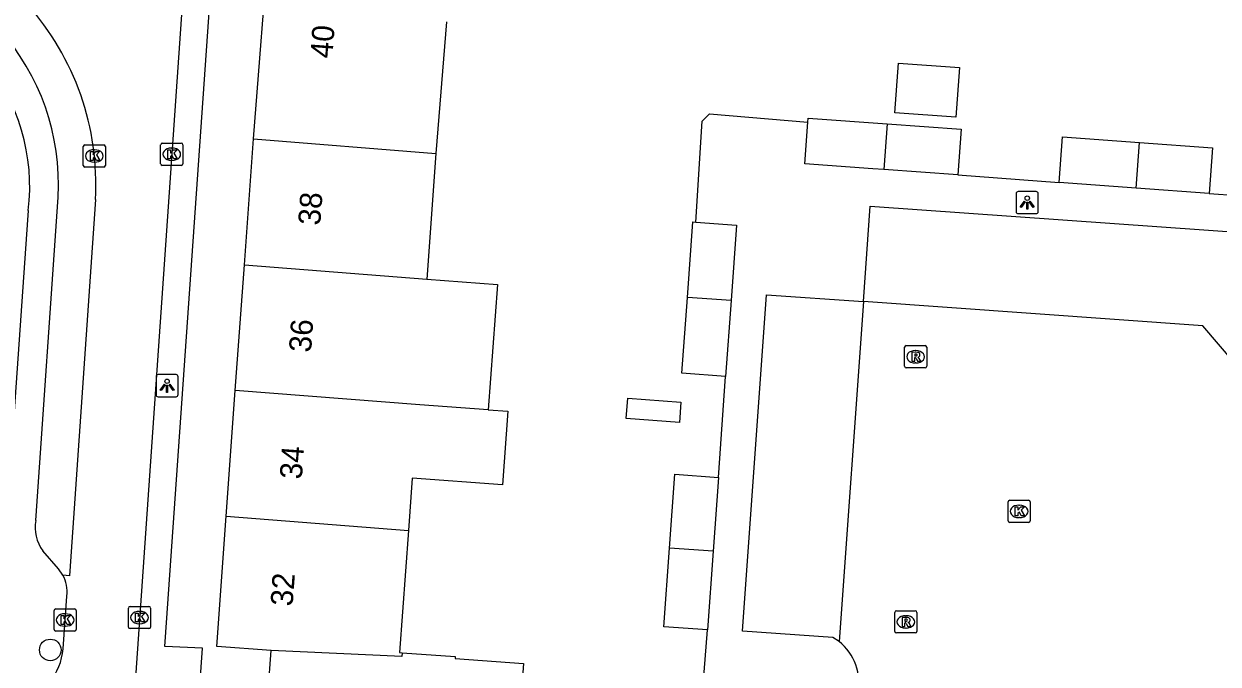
# Model space of a CAD drawing. Extents: x 160304 to 160954, y 383686 to 384161.
# Drawn here: x 160524.6 to 160578.4, y 384097.6 to 384126.5 of the extents above; entities that cross this region are included whole.
import ezdxf

# ---------------------------------------------------------------- set-up
doc = ezdxf.new("R2010")
doc.units = 0
for name, color, linetype in [('IMGEO_Boom', 7, 'Continuous'), ('IMGEO_Kolk', 7, 'Continuous'), ('IMGEO_Lichtpunt', 7, 'Continuous'), ('IMGEO_Pand', 7, 'Continuous'), ('IMGEO_Pand_nummerreeks', 7, 'Continuous'), ('IMGEO_Rijbaan_lokaal_open', 7, 'Continuous'), ('IMGEO_Rioolput', 7, 'Continuous'), ('IMGEO_Voetpad_open', 7, 'Continuous')]:
    doc.layers.add(name, color=color, linetype=linetype)

msp = doc.modelspace()

# ---------------------------------------------------------------- linework, layer by layer
at = {"layer": 'IMGEO_Boom'}
msp.add_circle((160525.753, 384098.271), 0.489, dxfattribs=at)
at = {"layer": 'IMGEO_Kolk'}
for p, q in [((160527.239, 384120.118), (160527.239, 384120.97)), ((160527.314, 384121.044), (160528.166, 384121.044)), ((160527.727, 384120.824), (160527.752, 384120.824)), ((160528.24, 384120.97), (160528.24, 384120.118)), ((160530.729, 384120.196), (160530.729, 384121.048)), ((160530.804, 384121.122), (160531.656, 384121.122)), ((160531.217, 384120.902), (160531.242, 384120.902)), ((160531.73, 384121.048), (160531.73, 384120.196)), ((160527.75, 384120.264), (160527.725, 384120.264)), ((160531.24, 384120.342), (160531.215, 384120.342)), ((160528.166, 384120.044), (160527.314, 384120.044)), ((160531.656, 384120.122), (160530.804, 384120.122)), ((160568.938, 384104.095), (160568.938, 384104.947)), ((160569.013, 384105.021), (160569.865, 384105.021)), ((160569.426, 384104.801), (160569.451, 384104.801)), ((160569.939, 384104.947), (160569.939, 384104.095)), ((160569.449, 384104.241), (160569.424, 384104.241)), ((160569.865, 384104.021), (160569.013, 384104.021)), ((160525.921, 384099.197), (160525.921, 384100.049)), ((160525.996, 384100.123), (160526.848, 384100.123)), ((160526.409, 384099.903), (160526.434, 384099.903)), ((160526.922, 384100.049), (160526.922, 384099.197)), ((160529.276, 384099.307), (160529.276, 384100.159)), ((160529.351, 384100.233), (160530.203, 384100.233)), ((160529.764, 384100.013), (160529.789, 384100.013)), ((160530.277, 384100.159), (160530.277, 384099.307)), ((160526.432, 384099.343), (160526.407, 384099.343)), ((160529.787, 384099.453), (160529.762, 384099.453)), ((160526.848, 384099.123), (160525.996, 384099.123)), ((160530.203, 384099.233), (160529.351, 384099.233))]:
    msp.add_line(p, q, dxfattribs=at)
for points in [[(160527.239, 384120.118), (160527.239, 384120.97)], [(160527.314, 384121.044), (160528.166, 384121.044)], [(160528.24, 384120.97), (160528.24, 384120.118)], [(160530.729, 384120.196), (160530.729, 384121.048)], [(160530.804, 384121.122), (160531.656, 384121.122)], [(160531.05, 384120.822), (160531.173, 384120.822), (160531.173, 384120.671), (160531.303, 384120.822), (160531.467, 384120.822), (160531.321, 384120.671), (160531.474, 384120.422), (160531.322, 384120.422), (160531.237, 384120.586), (160531.173, 384120.519), (160531.173, 384120.422), (160531.05, 384120.422), (160531.05, 384120.822)], [(160531.73, 384121.048), (160531.73, 384120.196)], [(160527.56, 384120.744), (160527.683, 384120.744), (160527.683, 384120.593), (160527.813, 384120.744), (160527.977, 384120.744), (160527.831, 384120.593), (160527.984, 384120.344), (160527.832, 384120.344), (160527.747, 384120.508), (160527.683, 384120.441), (160527.683, 384120.344), (160527.56, 384120.344), (160527.56, 384120.744)], [(160528.166, 384120.044), (160527.314, 384120.044)], [(160531.656, 384120.122), (160530.804, 384120.122)], [(160568.938, 384104.095), (160568.938, 384104.947)], [(160569.013, 384105.021), (160569.865, 384105.021)], [(160569.259, 384104.721), (160569.382, 384104.721), (160569.382, 384104.57), (160569.512, 384104.721), (160569.676, 384104.721), (160569.53, 384104.57), (160569.683, 384104.321), (160569.531, 384104.321), (160569.446, 384104.485), (160569.382, 384104.418), (160569.382, 384104.321), (160569.259, 384104.321), (160569.259, 384104.721)], [(160569.939, 384104.947), (160569.939, 384104.095)], [(160569.865, 384104.021), (160569.013, 384104.021)], [(160525.921, 384099.197), (160525.921, 384100.049)], [(160525.996, 384100.123), (160526.848, 384100.123)], [(160526.242, 384099.823), (160526.365, 384099.823), (160526.365, 384099.672), (160526.495, 384099.823), (160526.659, 384099.823), (160526.513, 384099.672), (160526.666, 384099.423), (160526.514, 384099.423), (160526.429, 384099.587), (160526.365, 384099.52), (160526.365, 384099.423), (160526.242, 384099.423), (160526.242, 384099.823)], [(160526.922, 384100.049), (160526.922, 384099.197)], [(160529.276, 384099.307), (160529.276, 384100.159)], [(160529.351, 384100.233), (160530.203, 384100.233)], [(160529.597, 384099.933), (160529.72, 384099.933), (160529.72, 384099.782), (160529.85, 384099.933), (160530.014, 384099.933), (160529.868, 384099.782), (160530.021, 384099.533), (160529.869, 384099.533), (160529.784, 384099.697), (160529.72, 384099.63), (160529.72, 384099.533), (160529.597, 384099.533), (160529.597, 384099.933)], [(160530.277, 384100.159), (160530.277, 384099.307)], [(160526.848, 384099.123), (160525.996, 384099.123)], [(160530.203, 384099.233), (160529.351, 384099.233)]]:
    msp.add_lwpolyline(points, dxfattribs=at)
for centre, start, end in [((160527.316, 384120.968), 91.552, 178.448), ((160527.316, 384120.968), 91.552, 178.448), ((160528.164, 384120.968), 1.552, 88.448), ((160528.164, 384120.968), 1.552, 88.448), ((160530.806, 384121.046), 91.552, 178.448), ((160530.806, 384121.046), 91.552, 178.448), ((160531.654, 384121.046), 1.552, 88.448), ((160531.654, 384121.046), 1.552, 88.448), ((160527.316, 384120.12), 181.552, 268.448), ((160527.316, 384120.12), 181.552, 268.448), ((160528.164, 384120.12), 271.552, 358.448), ((160528.164, 384120.12), 271.552, 358.448), ((160530.806, 384120.198), 181.552, 268.448), ((160530.806, 384120.198), 181.552, 268.448), ((160531.654, 384120.198), 271.552, 358.448), ((160531.654, 384120.198), 271.552, 358.448), ((160569.015, 384104.945), 91.552, 178.448), ((160569.015, 384104.945), 91.552, 178.448), ((160569.863, 384104.945), 1.552, 88.448), ((160569.863, 384104.945), 1.552, 88.448), ((160569.015, 384104.097), 181.552, 268.448), ((160569.015, 384104.097), 181.552, 268.448), ((160569.863, 384104.097), 271.552, 358.448), ((160569.863, 384104.097), 271.552, 358.448), ((160525.998, 384100.047), 91.552, 178.448), ((160525.998, 384100.047), 91.552, 178.448), ((160526.846, 384100.047), 1.552, 88.448), ((160526.846, 384100.047), 1.552, 88.448), ((160529.353, 384100.157), 91.552, 178.448), ((160529.353, 384100.157), 91.552, 178.448), ((160530.201, 384100.157), 1.552, 88.448), ((160530.201, 384100.157), 1.552, 88.448), ((160529.353, 384099.309), 181.552, 268.448), ((160529.353, 384099.309), 181.552, 268.448), ((160530.201, 384099.309), 271.552, 358.448), ((160530.201, 384099.309), 271.552, 358.448), ((160525.998, 384099.199), 181.552, 268.448), ((160525.998, 384099.199), 181.552, 268.448), ((160526.846, 384099.199), 271.552, 358.448), ((160526.846, 384099.199), 271.552, 358.448)]:
    msp.add_arc(centre, 0.0765, start, end, dxfattribs=at)
for centre, major_axis, ratio, start_param, end_param in [((160527.726, 384120.544), (-0.387, 0.002), 0.722429, 4.712389, 7.853982), ((160527.751, 384120.544), (-0.39, 0.002), 0.717154, 1.570796, 4.712389), ((160531.216, 384120.622), (-0.387, 0.002), 0.722429, 4.712389, 7.853982), ((160531.241, 384120.622), (-0.39, 0.002), 0.717154, 1.570796, 4.712389), ((160569.425, 384104.521), (-0.387, 0.002), 0.722429, 4.712389, 7.853982), ((160569.45, 384104.521), (-0.39, 0.002), 0.717154, 1.570796, 4.712389), ((160526.408, 384099.623), (-0.387, 0.002), 0.722429, 4.712389, 7.853982), ((160526.433, 384099.623), (-0.39, 0.002), 0.717154, 1.570796, 4.712389), ((160529.763, 384099.733), (-0.387, 0.002), 0.722429, 4.712389, 7.853982), ((160529.788, 384099.733), (-0.39, 0.002), 0.717154, 1.570796, 4.712389)]:
    msp.add_ellipse(centre, major_axis=major_axis, ratio=ratio, start_param=start_param, end_param=end_param, dxfattribs=at)
at = {"layer": 'IMGEO_Lichtpunt'}
for p, q in [((160569.302, 384118.845), (160569.302, 384118.038)), ((160569.302, 384118.845), (160569.302, 384118.038)), ((160570.204, 384118.94), (160569.396, 384118.94)), ((160570.204, 384118.94), (160569.396, 384118.94)), ((160570.298, 384118.038), (160570.298, 384118.845)), ((160570.298, 384118.038), (160570.298, 384118.845)), ((160569.396, 384117.944), (160570.204, 384117.944)), ((160569.396, 384117.944), (160570.204, 384117.944)), ((160530.521, 384110.59), (160530.521, 384109.783)), ((160530.521, 384110.59), (160530.521, 384109.783)), ((160531.423, 384110.685), (160530.615, 384110.685)), ((160531.423, 384110.685), (160530.615, 384110.685)), ((160531.517, 384109.783), (160531.517, 384110.59)), ((160531.517, 384109.783), (160531.517, 384110.59)), ((160530.615, 384109.689), (160531.423, 384109.689)), ((160530.615, 384109.689), (160531.423, 384109.689))]:
    msp.add_line(p, q, dxfattribs=at)
for points in [[(160569.676, 384118.509), (160569.715, 384118.481), (160569.527, 384118.219), (160569.489, 384118.246), (160569.676, 384118.509)], [(160569.778, 384118.461), (160569.825, 384118.461), (160569.825, 384118.139), (160569.778, 384118.139), (160569.778, 384118.461)], [(160569.888, 384118.481), (160569.926, 384118.508), (160570.113, 384118.246), (160570.074, 384118.218), (160569.888, 384118.481)], [(160530.895, 384110.254), (160530.934, 384110.226), (160530.746, 384109.964), (160530.708, 384109.991), (160530.895, 384110.254)], [(160530.997, 384110.206), (160531.044, 384110.206), (160531.044, 384109.884), (160530.997, 384109.884), (160530.997, 384110.206)], [(160531.107, 384110.226), (160531.145, 384110.253), (160531.332, 384109.991), (160531.293, 384109.963), (160531.107, 384110.226)]]:
    msp.add_lwpolyline(points, dxfattribs=at)
for centre in [(160569.801, 384118.643), (160531.02, 384110.388)]:
    msp.add_circle(centre, 0.0994, dxfattribs=at)
for centre, start, end in [((160569.396, 384118.845), 90, 180), ((160569.396, 384118.845), 90, 180), ((160570.204, 384118.845), 0, 90), ((160570.204, 384118.845), 0, 90), ((160569.396, 384118.038), 180, 270), ((160569.396, 384118.038), 180, 270), ((160570.204, 384118.038), 270, 0), ((160570.204, 384118.038), 270, 360), ((160530.615, 384110.59), 90, 180), ((160530.615, 384110.59), 90, 180), ((160531.423, 384110.59), 0, 90), ((160531.423, 384110.59), 0, 90), ((160530.615, 384109.783), 180, 270), ((160530.615, 384109.783), 180, 270), ((160531.423, 384109.783), 270, 0), ((160531.423, 384109.783), 270, 360)]:
    msp.add_arc(centre, 0.0946, start, end, dxfattribs=at)
at = {"layer": 'IMGEO_Pand'}
for points in [[(160534.918, 384121.312), (160535.658, 384130.704)], [(160543.616, 384126.592), (160543.136, 384120.655)], [(160563.834, 384122.489), (160563.993, 384124.731), (160566.742, 384124.537), (160566.584, 384122.294), (160563.834, 384122.489)], [(160563.338, 384119.93), (160562.837, 384119.966), (160559.78, 384120.188), (160559.916, 384122.067)], [(160559.916, 384122.067), (160559.93, 384122.255), (160563.484, 384121.997)], [(160563.484, 384121.997), (160563.338, 384119.93)], [(160563.484, 384121.997), (160566.826, 384121.755), (160566.676, 384119.688)], [(160571.242, 384119.346), (160571.391, 384121.402), (160574.859, 384121.151)], [(160534.507, 384115.643), (160534.918, 384121.312)], [(160534.918, 384121.312), (160543.136, 384120.655)], [(160574.718, 384119.094), (160574.859, 384121.151)], [(160574.859, 384121.151), (160578.16, 384120.912), (160578.011, 384118.856)], [(160543.136, 384120.655), (160542.725, 384114.987)], [(160566.676, 384119.688), (160563.338, 384119.93)], [(160574.718, 384119.094), (160571.242, 384119.346)], [(160578.011, 384118.856), (160574.718, 384119.094)], [(160554.476, 384114.169), (160554.723, 384117.573), (160554.858, 384117.563)], [(160554.858, 384117.563), (160556.695, 384117.43), (160556.449, 384114.031)], [(160534.096, 384109.976), (160534.507, 384115.643)], [(160534.507, 384115.643), (160542.725, 384114.987)], [(160542.725, 384114.987), (160545.913, 384114.756), (160545.503, 384109.097)], [(160556.2, 384110.603), (160554.227, 384110.746), (160554.476, 384114.169)], [(160556.449, 384114.031), (160554.476, 384114.169)], [(160556.449, 384114.031), (160556.2, 384110.603)], [(160533.684, 384104.304), (160534.096, 384109.976)], [(160545.503, 384109.097), (160542.41, 384109.32), (160534.096, 384109.976)], [(160554.116, 384108.53), (160551.725, 384108.704), (160551.792, 384109.625), (160554.183, 384109.451), (160554.116, 384108.53)], [(160545.503, 384109.097), (160546.387, 384109.033), (160546.147, 384105.723), (160542.074, 384106.018), (160541.903, 384103.658)], [(160553.675, 384102.864), (160553.916, 384106.191), (160555.881, 384106.048)], [(160555.881, 384106.048), (160555.641, 384102.731)], [(160535.71, 384098.248), (160533.258, 384098.425), (160533.684, 384104.304)], [(160533.684, 384104.304), (160541.903, 384103.658)], [(160541.903, 384103.658), (160541.504, 384098.152), (160541.621, 384098.144)], [(160555.383, 384099.177), (160553.418, 384099.32), (160553.675, 384102.864)], [(160555.641, 384102.731), (160553.675, 384102.864)], [(160555.641, 384102.731), (160555.383, 384099.177)], [(160535.311, 384092.74), (160535.71, 384098.248)], [(160541.621, 384098.144), (160541.61, 384097.97), (160535.71, 384098.248)], [(160541.621, 384098.144), (160544.014, 384097.97), (160544.008, 384097.884), (160547.083, 384097.661), (160546.654, 384091.741), (160543.578, 384091.964)]]:
    msp.add_lwpolyline(points, dxfattribs=at)
at = {"layer": 'IMGEO_Rijbaan_lokaal_open'}
for points in [[(160537.481, 384138.035), (160534.196, 384135.168), (160533.788, 384134.809), (160533.414, 384134.416), (160533.076, 384133.99), (160532.778, 384133.536), (160532.521, 384133.058), (160532.308, 384132.558), (160532.141, 384132.041), (160532.021, 384131.511), (160531.948, 384130.973), (160531.927, 384130.626), (160529.545, 384096.378), (160529.643, 384095.449)], [(160527.788, 384118.582), (160526.612, 384101.616), (160526.321, 384101.646)], [(160562.416, 384113.979), (160561.315, 384098.651)], [(160584.868, 384104.518), (160577.716, 384112.888), (160562.416, 384113.979)], [(160526.335, 384098.318), (160526.497, 384100.704)]]:
    msp.add_lwpolyline(points, dxfattribs=at)
for centre, radius, start, end in [((160515.64, 384119.275), 12.168, 356.7331, 41.8412), ((160524.968, 384100.906), 1.543, 352.4883, 28.6775), ((160523.525, 384098.596), 2.824, 320.8869, 354.3452), ((160559.948, 384096.863), 2.251, 345.8903, 52.6046)]:
    msp.add_arc(centre, radius, start, end, dxfattribs=at)
at = {"layer": 'IMGEO_Rioolput'}
for p, q in [((160564.268, 384111.066), (160564.268, 384111.918)), ((160564.343, 384111.992), (160565.195, 384111.992)), ((160564.756, 384111.772), (160564.781, 384111.772)), ((160565.269, 384111.918), (160565.269, 384111.066)), ((160564.779, 384111.212), (160564.754, 384111.212)), ((160565.195, 384110.992), (160564.343, 384110.992)), ((160563.828, 384099.111), (160563.828, 384099.963)), ((160563.903, 384100.037), (160564.755, 384100.037)), ((160564.316, 384099.817), (160564.341, 384099.817)), ((160564.829, 384099.963), (160564.829, 384099.111)), ((160564.339, 384099.257), (160564.314, 384099.257)), ((160564.755, 384099.037), (160563.903, 384099.037))]:
    msp.add_line(p, q, dxfattribs=at)
for points in [[(160564.268, 384111.066), (160564.268, 384111.918)], [(160564.343, 384111.992), (160565.195, 384111.992)], [(160564.857, 384111.69), (160564.605, 384111.692), (160564.605, 384111.292)], [(160565.269, 384111.918), (160565.269, 384111.066)], [(160564.605, 384111.292), (160564.729, 384111.292), (160564.729, 384111.454), (160564.74, 384111.454)], [(160564.783, 384111.611), (160564.729, 384111.611), (160564.729, 384111.53)], [(160564.729, 384111.53), (160564.781, 384111.53)], [(160564.787, 384111.425), (160564.858, 384111.292), (160564.998, 384111.292), (160564.933, 384111.418)], [(160565.195, 384110.992), (160564.343, 384110.992)], [(160563.828, 384099.111), (160563.828, 384099.963)], [(160563.903, 384100.037), (160564.755, 384100.037)], [(160564.829, 384099.963), (160564.829, 384099.111)], [(160564.417, 384099.735), (160564.165, 384099.737), (160564.165, 384099.337)], [(160564.165, 384099.337), (160564.289, 384099.337), (160564.289, 384099.499), (160564.3, 384099.499)], [(160564.343, 384099.656), (160564.289, 384099.656), (160564.289, 384099.575)], [(160564.289, 384099.575), (160564.341, 384099.575)], [(160564.347, 384099.47), (160564.418, 384099.337), (160564.558, 384099.337), (160564.493, 384099.463)], [(160564.755, 384099.037), (160563.903, 384099.037)]]:
    msp.add_lwpolyline(points, dxfattribs=at)
for centre, radius, start, end in [((160564.345, 384111.916), 0.0765, 91.552, 178.448), ((160564.345, 384111.916), 0.0765, 91.552, 178.448), ((160564.856, 384111.58), 0.109, 350.3612, 89.416), ((160565.193, 384111.916), 0.0765, 1.552, 88.448), ((160565.193, 384111.916), 0.0765, 1.552, 88.448), ((160564.739, 384111.401), 0.0533, 26.0293, 88.6989), ((160564.765, 384111.719), 0.19, 274.7715, 282.9687), ((160564.789, 384111.515), 0.0964, 77.0061, 93.1865), ((160564.803, 384111.572), 0.0378, 276.6634, 79.6772), ((160564.854, 384111.58), 0.112, 277.5842, 350.9817), ((160564.838, 384111.365), 0.108, 29.5134, 73.7905), ((160564.345, 384111.068), 0.0765, 181.552, 268.448), ((160564.345, 384111.068), 0.0765, 181.552, 268.448), ((160565.193, 384111.068), 0.0765, 271.552, 358.448), ((160565.193, 384111.068), 0.0765, 271.552, 358.448), ((160563.905, 384099.961), 0.0765, 91.552, 178.448), ((160563.905, 384099.961), 0.0765, 91.552, 178.448), ((160564.753, 384099.961), 0.0765, 1.552, 88.448), ((160564.753, 384099.961), 0.0765, 1.552, 88.448), ((160564.299, 384099.446), 0.0533, 26.0293, 88.6989), ((160564.325, 384099.764), 0.19, 274.7715, 282.9687), ((160564.349, 384099.56), 0.0964, 77.0061, 93.1865), ((160564.363, 384099.617), 0.0378, 276.6634, 79.6772), ((160564.416, 384099.625), 0.109, 350.3612, 89.416), ((160564.414, 384099.625), 0.112, 277.5842, 350.9817), ((160564.398, 384099.41), 0.108, 29.5134, 73.7905), ((160563.905, 384099.113), 0.0765, 181.552, 268.448), ((160563.905, 384099.113), 0.0765, 181.552, 268.448), ((160564.753, 384099.113), 0.0765, 271.552, 358.448), ((160564.753, 384099.113), 0.0765, 271.552, 358.448)]:
    msp.add_arc(centre, radius, start, end, dxfattribs=at)
for centre, major_axis, ratio, start_param, end_param in [((160564.755, 384111.492), (-0.387, 0.002), 0.722429, 4.712389, 7.853982), ((160564.78, 384111.492), (-0.39, 0.002), 0.717154, 1.570796, 4.712389), ((160564.315, 384099.537), (-0.387, 0.002), 0.722429, 4.712389, 7.853982), ((160564.34, 384099.537), (-0.39, 0.002), 0.717154, 1.570796, 4.712389)]:
    msp.add_ellipse(centre, major_axis=major_axis, ratio=ratio, start_param=start_param, end_param=end_param, dxfattribs=at)
at = {"layer": 'IMGEO_Voetpad_open'}
for points in [[(160530.227, 384064.308), (160532.622, 384098.352), (160530.921, 384098.428), (160533.173, 384130.684), (160533.182, 384130.784), (160533.255, 384131.273), (160533.37, 384131.754), (160533.529, 384132.222), (160533.728, 384132.674), (160533.967, 384133.107), (160534.244, 384133.516), (160534.556, 384133.899), (160534.901, 384134.253), (160548.216, 384145.882), (160548.855, 384146.134)], [(160554.858, 384117.563), (160555.144, 384122.114), (160555.479, 384122.44), (160559.916, 384122.067)], [(160566.676, 384119.688), (160571.242, 384119.346)], [(160525.095, 384104.114), (160526.106, 384118.694)], [(160578.011, 384118.856), (160580.556, 384118.677), (160582.288, 384116.741)], [(160562.416, 384113.979), (160562.725, 384118.281), (160580.09, 384117.043), (160587.68, 384108.161)], [(160524.758, 384118.081), (160523.413, 384099.123), (160521.599, 384099.239), (160519.191, 384065.161)], [(160561.315, 384098.651), (160561.039, 384098.832), (160556.961, 384099.125), (160558.051, 384114.29), (160562.416, 384113.979)], [(160555.881, 384106.048), (160556.2, 384110.603)], [(160526.321, 384101.646), (160526.123, 384101.93), (160525.414, 384102.742)], [(160554.982, 384094.025), (160555.383, 384099.177)]]:
    msp.add_lwpolyline(points, dxfattribs=at)
for centre, radius, start, end in [((160515.632, 384119.272), 10.49, 356.8423, 41.8072), ((160515.931, 384119.178), 8.895, 352.9157, 40.1997), ((160526.885, 384103.807), 1.816, 170.2677, 215.9106)]:
    msp.add_arc(centre, radius, start, end, dxfattribs=at)

# ---------------------------------------------------------------- texts
at = {"layer": 'IMGEO_Pand_nummerreeks'}
for s, p in [('40', (160538.468, 384124.922)), ('38', (160537.922, 384117.393)), ('36', (160537.507, 384111.668)), ('34', (160537.092, 384105.946)), ('32', (160536.677, 384100.221))]:
    msp.add_text(s, height=1, rotation=85.852, dxfattribs=at).set_placement(p)

doc.saveas('drawing.dxf')
